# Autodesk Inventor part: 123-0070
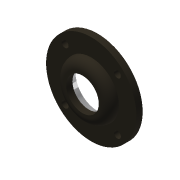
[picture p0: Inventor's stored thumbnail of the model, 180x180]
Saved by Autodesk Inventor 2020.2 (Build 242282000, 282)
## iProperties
Created: 2006-03
Part Number: 123-0070
Document SubType Name: Modeling
Designer: F.Stasiak
Description: Pokrywka typ 2
Material: St 4S
Project: Przekładnia X51
Mass: 155.323 g
Surface Area: 100.762 cm^2
Volume: 19.7864 cm^3
Density: 7.85 g/cm^3
Appearance: Brąz armatni (nowy/polerowany)
Manager: www.cadconsulting.pl
Company: Fabian Stasiak CAD Consulting
Author: F.Stasiak
Subject: Zbiór ćwiczeń. Autodesk Inventor 2020. Kurs podstawowy
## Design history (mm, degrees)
sketch "Szkic1"
  geometry: L1 (17.5, 0)-(17.5, -7); L2 (17.5, -7)-(13, -7); L3 (13, -7)-(13, -12); L4 (36, 0)-(17.5, 0); L5 (0, -12)-(0, 0); L6 (13, -12)-(15, -12); L7 (22, -5)-(36, -5); L8 (36, -5)-(36, 0); L9 (22, -5)-(17.5, -5); L10 (13, -12)-(0, -12); L11 (17.5, 0)-(0, 0); A1 r 7 centre (15, -5) between (15, -12) and (22, -5); 1 further point
  constraints: 22 end point, 5 perpendicular, 4 parallel, 2 point on circle, 2 point on line, 1 centre point, 1 coincident, 1 horizontal, 1 tangent, 1 vertical
  dimensions: "d0" = 35 diameter of L1 L5; "d1" = 26 diameter of L3 L5; "d3" = 72 diameter of L8 L5; "d4" = 7 distance of L1.start L1.end; "d5" = 5 distance of L7.end L4.start; "d6" = 12 distance between parallel lines of L6 L4; "d13" = 14 distance from line of L7.start L8
revolve "Obrót1" sketch "Szkic1" stored, may be unused: angle "d14" = 90 deg
sketch "Szkic2" dims "d16" = 59
  geometry: L1 (0, 0)-(-25.456, -25.456); L2 (0, 0)-(0, -36); A1 r 36 centre (0, 0) between (-25.456, -25.456) and (0, -36) reference; 3 further points
  constraints: 4 end point, 2 point on circle, 1 coincident, 1 point on line, 1 vertical, 3 other
  dimensions: "d15" = 45 deg angle of L2 L1
hole "Otwór1" sketch "Szkic2" at (-20.86, -20.86) diameter "d17" = 5.5; stored, may be unused: countersink angle "d21" = 90 deg, drill point angle "d23" = 118 deg; dims "d18" = 6, "d19" = 4, "d20" = 2, "d22" = 8
pattern_circular "Szyk kołowy1" dims angle "d25" = 360 deg
node "Bryła1"
node "Korpusy bryłowe"
node "Korpusy powierzchniowe"
